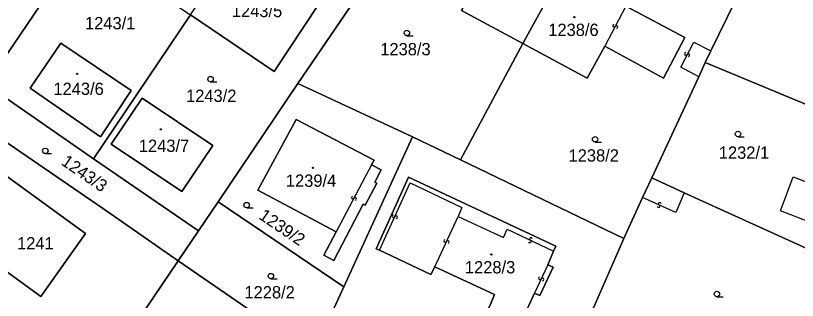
# Model space of a CAD drawing. Extents: x -600309 to -598967, y -1161267 to -1160292.
# Drawn here: x -600216.2 to -600108.2, y -1160403.9 to -1160364.7 of the extents above; entities that cross this region are included whole.
import ezdxf

# ---------------------------------------------------------------- set-up
doc = ezdxf.new("R2010")
doc.units = 0
for name, color, linetype in [('Level 1', 7, 'Continuous'), ('Level 13', 7, 'Continuous'), ('Level 3', 7, 'Continuous'), ('Level 4', 7, 'Continuous'), ('Level 5', 7, 'Continuous'), ('Level 60', 7, 'Continuous')]:
    doc.layers.add(name, color=color, linetype=linetype)

msp = doc.modelspace()

# ---------------------------------------------------------------- linework, layer by layer
at = {"layer": 'Level 1'}
for points in [[(-600220.24, -1160374.15), (-600199.77, -1160343.98)], [(-600140.75, -1160358.71), (-600149.16, -1160354.14), (-600154.59, -1160363.97), (-600146.15, -1160368.53)], [(-600192.04, -1160364.57), (-600180.49, -1160372.35), (-600174.33, -1160363.14), (-600185.89, -1160355.37)], [(-600146.15, -1160368.53), (-600140.75, -1160358.71)], [(-600177.18, -1160374.01), (-600170.09, -1160363.59)], [(-600131.94, -1160363.38), (-600123.79, -1160367.67), (-600126.71, -1160373.31), (-600134.84, -1160368.89)], [(-600120.18, -1160369.53), (-600116.85, -1160362.66)], [(-600205.39, -1160384.4), (-600199.44, -1160375.52), (-600192.04, -1160364.57)], [(-600204.45, -1160381.38), (-600200.2, -1160375.01), (-600209.93, -1160368.46), (-600214.13, -1160374.69), (-600204.45, -1160381.38)], [(-600154.74, -1160384.57), (-600146.15, -1160368.53)], [(-600146.15, -1160368.53), (-600137.27, -1160373.27), (-600134.84, -1160368.89)], [(-600120.98, -1160371.11), (-600120.18, -1160369.53)], [(-600121.87, -1160373.11), (-600120.98, -1160371.11)], [(-600120.98, -1160371.11), (-600104.7, -1160377.9)], [(-600128.33, -1160387.05), (-600121.87, -1160373.11)], [(-600220.24, -1160374.15), (-600205.39, -1160384.4)], [(-600188.22, -1160390.36), (-600177.18, -1160374.01)], [(-600161.35, -1160381.39), (-600177.18, -1160374.01)], [(-600198.68, -1160376.04), (-600188.94, -1160382.59), (-600193.21, -1160388.94), (-600202.95, -1160382.38), (-600198.68, -1160376.04)], [(-600171.89, -1160394.48), (-600182.71, -1160388.76), (-600177.45, -1160378.99), (-600166.68, -1160384.62), (-600167.01, -1160385.25)], [(-600235.83, -1160413.97), (-600237.42, -1160405.71), (-600220.3, -1160380.18), (-600204.05, -1160391.32), (-600193.72, -1160398.49)], [(-600170.86, -1160402.06), (-600161.35, -1160381.39)], [(-600161.35, -1160381.39), (-600154.74, -1160384.57)], [(-600205.39, -1160384.4), (-600190.91, -1160394.34)], [(-600154.74, -1160384.57), (-600132.22, -1160395.43)], [(-600167.01, -1160385.25), (-600165.68, -1160385.95), (-600166.57, -1160387.63), (-600166.29, -1160387.79), (-600167.89, -1160390.82), (-600168.18, -1160390.65), (-600172.25, -1160398.44), (-600173.6, -1160397.73), (-600171.89, -1160394.48)], [(-600212.69, -1160403.4), (-600221.56, -1160396.97), (-600218.35, -1160392.37), (-600220.87, -1160390.5), (-600217.96, -1160386.41), (-600206.49, -1160394.71), (-600212.69, -1160403.4)], [(-600141.89, -1160397.15), (-600141.58, -1160396.47), (-600161.94, -1160386.95), (-600166.41, -1160396.83), (-600165.93, -1160397.04)], [(-600129.61, -1160389.74), (-600128.33, -1160387.05)], [(-600128.33, -1160387.05), (-600123.85, -1160389.12)], [(-600123.85, -1160389.12), (-600079.98, -1160409.03)], [(-600190.91, -1160394.34), (-600188.22, -1160390.36)], [(-600188.22, -1160390.36), (-600170.86, -1160402.06)], [(-600132.22, -1160395.43), (-600129.61, -1160389.74)], [(-600193.72, -1160398.49), (-600190.91, -1160394.34)], [(-600132.22, -1160395.43), (-600137.66, -1160407.91)], [(-600158.28, -1160399.31), (-600158.84, -1160400.36), (-600165.93, -1160397.04)], [(-600141.89, -1160397.15), (-600142.71, -1160399.03)], [(-600215.73, -1160431), (-600193.72, -1160398.49)], [(-600194.23, -1160441.01), (-600187.93, -1160431.9), (-600177.92, -1160409.34), (-600193.72, -1160398.49)], [(-600142.71, -1160399.03), (-600141.97, -1160399.38), (-600143.81, -1160403.28), (-600144.52, -1160402.93)], [(-600150.58, -1160404.38), (-600150.07, -1160403.15), (-600158.28, -1160399.31)], [(-600196.86, -1160449.84), (-600185.43, -1160433.77), (-600170.86, -1160402.06)], [(-600144.52, -1160402.93), (-600146.15, -1160406.46)]]:
    msp.add_lwpolyline(points, dxfattribs=at)
at = {"layer": 'Level 13'}
for centre, start, end in [((-600133.55, -1160366.05), 99.3997, 331.9897), ((-600133.23, -1160366.23), 279.6142, 151.7122), ((-600123.62, -1160369.95), 99.9506, 332.0486), ((-600123.3, -1160370.13), 279.7362, 152.3262), ((-600169.61, -1160389.77), 99.2924, 331.8824), ((-600169.29, -1160389.95), 279.5068, 151.6048), ((-600127.24, -1160390.62), 12.4786, 245.0686), ((-600127.4, -1160390.96), 192.6931, 64.7911), ((-600163.99, -1160392.32), 102.8916, 334.9896), ((-600163.65, -1160392.48), 282.6772, 155.2672), ((-600156.85, -1160395.75), 102.6812, 334.7792), ((-600156.51, -1160395.91), 282.4667, 155.0567), ((-600145.18, -1160395.81), 192.0389, 64.6289), ((-600145.02, -1160395.47), 12.2533, 244.3513), ((-600143.79, -1160400.9), 102.2621, 334.8521), ((-600143.45, -1160401.06), 282.4766, 154.5746)]:
    msp.add_arc(centre, 0.184, start, end, dxfattribs=at)
at = {"layer": 'Level 3'}
for points in [[(-600131.94, -1160363.38), (-600134.84, -1160368.89)], [(-600121.87, -1160373.11), (-600124.35, -1160371.76), (-600122.56, -1160368.31), (-600120.18, -1160369.53)], [(-600167.01, -1160385.25), (-600171.89, -1160394.48)], [(-600098.38, -1160390.95), (-600100.13, -1160395.62), (-600110.57, -1160391.57), (-600108.81, -1160386.91), (-600098.38, -1160390.95)], [(-600165.93, -1160397.04), (-600161.7, -1160387.75), (-600154.54, -1160391.14), (-600155.08, -1160392.35)], [(-600123.85, -1160389.12), (-600125.04, -1160391.84), (-600129.61, -1160389.74)], [(-600158.28, -1160399.31), (-600155.08, -1160392.35)], [(-600155.08, -1160392.35), (-600148.81, -1160395.28), (-600148.31, -1160394.14), (-600141.89, -1160397.15)], [(-600142.71, -1160399.03), (-600144.52, -1160402.93)]]:
    msp.add_lwpolyline(points, dxfattribs=at)
at = {"layer": 'Level 5'}
for p, q in [((-600162.15, -1160367.44), (-600161.28, -1160367.44)), ((-600189.25, -1160373.8), (-600188.38, -1160373.8)), ((-600116.44, -1160381.37), (-600115.57, -1160381.37)), ((-600136.17, -1160382.1), (-600135.3, -1160382.1)), ((-600212.06, -1160383.7), (-600211.19, -1160383.7)), ((-600184.26, -1160391.18), (-600183.39, -1160391.18)), ((-600180.92, -1160400.97), (-600180.05, -1160400.97)), ((-600119.35, -1160403.45), (-600118.47, -1160403.45))]:
    msp.add_line(p, q, dxfattribs=at)
for centre, radius in [((-600139.03, -1160364.87), 0.09), ((-600139.03, -1160364.87), 0.0521), ((-600162.15, -1160367.06), 0.375), ((-600207.66, -1160372.7), 0.09), ((-600207.66, -1160372.7), 0.0521), ((-600189.25, -1160373.42), 0.375), ((-600196.11, -1160380.35), 0.09), ((-600196.11, -1160380.35), 0.0521), ((-600116.44, -1160380.99), 0.375), ((-600136.17, -1160381.72), 0.375), ((-600212.06, -1160383.32), 0.375), ((-600175.1, -1160385.66), 0.09), ((-600175.1, -1160385.66), 0.0521), ((-600184.26, -1160390.8), 0.375), ((-600150.48, -1160397.62), 0.09), ((-600150.48, -1160397.62), 0.0521), ((-600180.92, -1160400.59), 0.375), ((-600119.35, -1160403.07), 0.375)]:
    msp.add_circle(centre, radius, dxfattribs=at)
at = {"layer": 'Level 60'}
for points in [[(-600104.7, -1160377.9), (-600120.98, -1160371.11), (-600120.18, -1160369.53), (-600116.85, -1160362.66), (-600101.04, -1160329.77), (-600099.82, -1160327.19), (-600097.18, -1160328.38), (-600093.61, -1160330.02), (-600090.66, -1160331.47), (-600091.3, -1160332.74), (-600092.68, -1160335.65), (-600094.66, -1160334.7), (-600095.18, -1160335.75), (-600098.92, -1160333.99), (-600099.7, -1160333.66), (-600107.49, -1160350.55), (-600100.41, -1160354.16), (-600099.25, -1160354.8), (-600090.52, -1160359.24), (-600094.42, -1160367.7), (-600100.13, -1160379.84), (-600101.76, -1160379.12)], [(-600243.16, -1160407.61), (-600244.73, -1160406.23), (-600247.25, -1160404.22), (-600250.43, -1160401.59), (-600259.8, -1160394.03), (-600260.37, -1160393.54), (-600263.15, -1160391.32), (-600262.97, -1160391.13), (-600221.27, -1160329.87), (-600199.77, -1160343.98), (-600220.24, -1160374.15), (-600223.07, -1160378.32), (-600242.98, -1160407.4)], [(-600220.24, -1160374.15), (-600199.77, -1160343.98), (-600184.93, -1160353.79), (-600185.89, -1160355.37), (-600197.45, -1160347.61), (-600203.6, -1160356.82), (-600192.04, -1160364.57), (-600199.44, -1160375.52), (-600205.39, -1160384.4)], [(-600154.74, -1160384.57), (-600161.35, -1160381.39), (-600177.18, -1160374.01), (-600170.09, -1160363.59), (-600163.92, -1160353.41), (-600160.44, -1160355.51), (-600156.74, -1160349.46), (-600160.25, -1160347.33), (-600158.5, -1160344.44), (-600155.37, -1160346.02), (-600154.53, -1160349.05), (-600148.82, -1160350.61), (-600139.05, -1160355.58), (-600140.75, -1160358.71), (-600149.16, -1160354.14), (-600154.59, -1160363.97), (-600146.15, -1160368.53)], [(-600170.09, -1160363.59), (-600177.18, -1160374.01), (-600188.22, -1160390.36), (-600190.91, -1160394.34), (-600205.39, -1160384.4), (-600199.44, -1160375.52), (-600192.04, -1160364.57), (-600180.49, -1160372.35), (-600174.33, -1160363.14), (-600185.89, -1160355.37), (-600184.93, -1160353.79)], [(-600132.22, -1160395.43), (-600154.74, -1160384.57), (-600146.15, -1160368.53), (-600137.27, -1160373.27), (-600134.84, -1160368.89), (-600126.71, -1160373.31), (-600123.79, -1160367.67), (-600131.94, -1160363.38), (-600140.75, -1160358.71), (-600139.05, -1160355.58), (-600138.81, -1160355.13), (-600138.51, -1160354.53), (-600134.91, -1160356.34), (-600134.35, -1160355.25), (-600116.85, -1160362.66), (-600120.18, -1160369.53), (-600120.98, -1160371.11), (-600121.87, -1160373.11), (-600128.33, -1160387.05), (-600129.61, -1160389.74)], [(-600149.16, -1160354.14), (-600140.75, -1160358.71), (-600146.15, -1160368.53), (-600154.59, -1160363.97)], [(-600174.33, -1160363.14), (-600180.49, -1160372.35), (-600192.04, -1160364.57), (-600185.89, -1160355.37)], [(-600137.27, -1160373.27), (-600146.15, -1160368.53), (-600140.75, -1160358.71), (-600131.94, -1160363.38), (-600123.79, -1160367.67), (-600126.71, -1160373.31), (-600134.84, -1160368.89)], [(-600123.85, -1160389.12), (-600128.33, -1160387.05), (-600121.87, -1160373.11), (-600120.98, -1160371.11), (-600104.7, -1160377.9), (-600101.76, -1160379.12), (-600100.13, -1160379.84), (-600094.42, -1160367.7), (-600078.2, -1160374.61), (-600079.47, -1160377.4), (-600066.98, -1160381.77), (-600066.57, -1160381.89), (-600070.67, -1160390.26), (-600074.83, -1160399.04), (-600076.23, -1160402.09), (-600079.56, -1160409.29), (-600079.85, -1160409.12), (-600079.98, -1160409.03)], [(-600204.45, -1160381.38), (-600214.13, -1160374.69), (-600209.93, -1160368.46), (-600200.2, -1160375.01)], [(-600204.45, -1160381.38), (-600200.2, -1160375.01), (-600209.93, -1160368.46), (-600214.13, -1160374.69)], [(-600243.16, -1160407.61), (-600242.98, -1160407.4), (-600223.07, -1160378.32), (-600220.24, -1160374.15), (-600205.39, -1160384.4), (-600190.91, -1160394.34), (-600193.72, -1160398.49), (-600204.05, -1160391.32), (-600220.3, -1160380.18), (-600237.42, -1160405.71), (-600235.83, -1160413.97)], [(-600161.35, -1160381.39), (-600170.86, -1160402.06), (-600188.22, -1160390.36), (-600177.18, -1160374.01)], [(-600198.68, -1160376.04), (-600188.94, -1160382.59), (-600193.21, -1160388.94), (-600202.95, -1160382.38)], [(-600198.68, -1160376.04), (-600202.95, -1160382.38), (-600193.21, -1160388.94), (-600188.94, -1160382.59)], [(-600172.25, -1160398.44), (-600173.6, -1160397.73), (-600171.89, -1160394.48), (-600182.71, -1160388.76), (-600177.45, -1160378.99), (-600166.68, -1160384.62), (-600167.01, -1160385.25), (-600165.68, -1160385.95), (-600166.57, -1160387.63), (-600166.29, -1160387.79), (-600167.89, -1160390.82), (-600168.18, -1160390.65)], [(-600173.6, -1160397.73), (-600172.25, -1160398.44), (-600168.18, -1160390.65), (-600167.89, -1160390.82), (-600166.29, -1160387.79), (-600166.57, -1160387.63), (-600165.68, -1160385.95), (-600167.01, -1160385.25), (-600166.68, -1160384.62), (-600177.45, -1160378.99), (-600182.71, -1160388.76), (-600171.89, -1160394.48)], [(-600215.73, -1160431), (-600215.99, -1160431.39), (-600235.83, -1160413.97), (-600237.42, -1160405.71), (-600220.3, -1160380.18), (-600204.05, -1160391.32), (-600193.72, -1160398.49)], [(-600137.66, -1160407.91), (-600148.04, -1160430.37), (-600168.28, -1160422.18), (-600173.84, -1160419.93), (-600182.99, -1160435.51), (-600194.67, -1160451.93), (-600196.86, -1160449.84), (-600185.43, -1160433.77), (-600170.86, -1160402.06), (-600161.35, -1160381.39), (-600154.74, -1160384.57), (-600132.22, -1160395.43)], [(-600212.69, -1160403.4), (-600221.56, -1160396.97), (-600218.35, -1160392.37), (-600220.87, -1160390.5), (-600217.96, -1160386.41), (-600206.49, -1160394.71)], [(-600221.56, -1160396.97), (-600212.69, -1160403.4), (-600206.49, -1160394.71), (-600217.96, -1160386.41), (-600220.87, -1160390.5), (-600218.35, -1160392.37)], [(-600141.58, -1160396.47), (-600141.89, -1160397.15), (-600142.71, -1160399.03), (-600141.97, -1160399.38), (-600143.81, -1160403.28), (-600144.52, -1160402.93), (-600146.15, -1160406.46), (-600145.95, -1160406.61), (-600146.49, -1160407.22), (-600145.39, -1160408.56), (-600142.1, -1160410.31), (-600142.55, -1160411.3), (-600144.5, -1160415.38), (-600152.28, -1160411.75), (-600153.75, -1160410.99), (-600150.58, -1160404.38), (-600150.07, -1160403.15), (-600158.28, -1160399.31), (-600158.84, -1160400.36), (-600165.93, -1160397.04), (-600166.41, -1160396.83), (-600161.94, -1160386.95)], [(-600141.89, -1160397.15), (-600141.58, -1160396.47), (-600161.94, -1160386.95), (-600166.41, -1160396.83), (-600165.93, -1160397.04), (-600158.84, -1160400.36), (-600158.28, -1160399.31), (-600150.07, -1160403.15), (-600150.58, -1160404.38), (-600153.75, -1160410.99), (-600152.28, -1160411.75), (-600144.5, -1160415.38), (-600142.55, -1160411.3), (-600142.1, -1160410.31), (-600145.39, -1160408.56), (-600146.49, -1160407.22), (-600145.95, -1160406.61), (-600146.15, -1160406.46), (-600144.52, -1160402.93), (-600143.81, -1160403.28), (-600141.97, -1160399.38), (-600142.71, -1160399.03)], [(-600089.16, -1160430.27), (-600089.68, -1160429.98), (-600103.87, -1160423.49), (-600104.07, -1160423.39), (-600111.18, -1160420.12), (-600117.59, -1160417.16), (-600127.7, -1160412.49), (-600137.66, -1160407.91), (-600132.22, -1160395.43), (-600129.61, -1160389.74), (-600128.33, -1160387.05), (-600123.85, -1160389.12), (-600079.98, -1160409.03), (-600079.85, -1160409.12), (-600079.56, -1160409.29)], [(-600185.43, -1160433.77), (-600196.86, -1160449.84), (-600199.13, -1160447.71), (-600198.88, -1160447.32), (-600194.23, -1160441.01), (-600187.93, -1160431.9), (-600177.92, -1160409.34), (-600193.72, -1160398.49), (-600190.91, -1160394.34), (-600188.22, -1160390.36), (-600170.86, -1160402.06)]]:
    msp.add_lwpolyline(points, close=True, dxfattribs=at)
msp.add_lwpolyline([(-600215.73, -1160431), (-600193.72, -1160398.49), (-600177.92, -1160409.34)], dxfattribs=at)

# ---------------------------------------------------------------- texts
at = {"layer": 'Level 4'}
for s, p in [('1243/5', (-600186.31, -1160364.87)), ('1243/1', (-600206.58, -1160366.55)), ('1238/6', (-600142.63, -1160367.47)), ('1238/3', (-600165.82, -1160370.14)), ('1243/6', (-600210.94, -1160375.61)), ('1243/2', (-600192.63, -1160376.57)), ('1243/7', (-600199.15, -1160383.47)), ('1238/2', (-600139.83, -1160384.8)), ('1232/1', (-600119.09, -1160384.41)), ('1239/4', (-600178.85, -1160388.28)), ('1241', (-600215.96, -1160396.92)), ('1228/3', (-600154.14, -1160400.22)), ('1228/2', (-600184.57, -1160403.67))]:
    msp.add_text(s, height=1.7, dxfattribs=at).set_placement(p)
for s, rotation, p in [('1243/3', 325.3896, (-600209.99, -1160385.14)), ('1239/2', 325.8, (-600182.71, -1160392.6))]:
    msp.add_text(s, height=1.7, rotation=rotation, dxfattribs=at).set_placement(p)

doc.saveas('drawing.dxf')
